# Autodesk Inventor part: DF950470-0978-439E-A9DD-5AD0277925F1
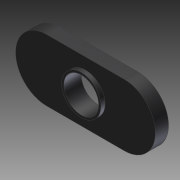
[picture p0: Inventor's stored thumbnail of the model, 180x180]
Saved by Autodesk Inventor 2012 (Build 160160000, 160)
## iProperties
Created: 2012-09
Part Number: DF950470-0978-439E-A9DD-5AD0277925F1
Material: Steel
Document SubType Name: Modeling
Designer: Owner
Density: 7.85 g/cm^3
Mass: 4.34909 g
Surface Area: 6.87932 cm^2
Volume: 0.554024 cm^3
Translation Standard: STEP AP214IS
FileName: DF950470-0978-439E-A9DD-5AD0277925F1.STEP
PreProcessor: SolidWorks 2008
PostProcessor: Build: 160, Release: 2012 RTM - Date: Tue 03/01/2011
Sent Units: inch
Uncertainty: 1e-05
Author: Owner
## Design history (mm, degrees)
node "DF950470-0978-439E-A9DD-5AD0277925F11"
node "NONE"
node "Base1"
